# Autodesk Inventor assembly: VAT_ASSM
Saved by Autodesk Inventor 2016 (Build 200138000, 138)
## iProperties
Created: 2016-03
Part Number: VAT_ASSM
Document SubType Name: Assembly
Designer: bongo_000
Author: bongo_000
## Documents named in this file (7)
- C:\Users\bongo_000\Downloads\DLP\VAT_ASSM.iam
- C:\Users\bongo_000\Downloads\DLP\Base.ipt
- C:\Users\bongo_000\Downloads\DLP\3D_Riser.ipt
- C:\Users\bongo_000\Downloads\DLP\FEP_FILM.ipt
- C:\Users\bongo_000\Downloads\DLP\Top_Clamp.ipt
- C:\Users\bongo_000\Downloads\DLP\Vat_Wall.ipt
- C:\Users\bongo_000\Downloads\DLP\Bottom_Clamp.ipt
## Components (9 placed, 9 different names)
1. Base_1061
2. 3D_Riser_1062
3. FEP_FILM_1063
4. Top_Clamp_1064
5. Vat_Wall_1065
6. Bottom_Clamp_1066
7. Vat_Wall_1067
8. Vat_Wall_1068
9. Vat_Wall_1069
